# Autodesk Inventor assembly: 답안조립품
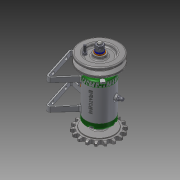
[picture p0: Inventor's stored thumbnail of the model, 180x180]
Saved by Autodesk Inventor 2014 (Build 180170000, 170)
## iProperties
Created: 2016-03
Part Number: 답안조립품
Document SubType Name: Assembly
Designer: SEC
Author: SEC
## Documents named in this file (16)
- C:\Documents and Settings\SEC\바탕 화면\460307V1022\답안조립품.iam
- C:\Documents and Settings\SEC\바탕 화면\460307V1022\본체.ipt
- C:\Documents and Settings\SEC\바탕 화면\460307V1022\V벨트풀리.ipt
- C:\Documents and Settings\SEC\바탕 화면\460307V1022\너트 M 8.ipt
- C:\Documents and Settings\SEC\바탕 화면\460307V1022\니플 M 6 x 0.75.ipt
- C:\Documents and Settings\SEC\바탕 화면\460307V1022\베어링 15 x 32 x 9.ipt
- C:\Documents and Settings\SEC\바탕 화면\460307V1022\볼트 M4 x 12.ipt
- C:\Documents and Settings\SEC\바탕 화면\460307V1022\볼트 M 6 x 8.ipt
- C:\Documents and Settings\SEC\바탕 화면\460307V1022\스프로킷.ipt
- C:\Documents and Settings\SEC\바탕 화면\460307V1022\스프링와셔 8.ipt
- C:\Documents and Settings\SEC\바탕 화면\460307V1022\오일 실 15 25 7.ipt
- C:\Documents and Settings\SEC\바탕 화면\460307V1022\와셔 6x11.5.ipt
- C:\Documents and Settings\SEC\바탕 화면\460307V1022\와셔 8x17.ipt
- C:\Documents and Settings\SEC\바탕 화면\460307V1022\축.ipt
- C:\Documents and Settings\SEC\바탕 화면\460307V1022\커버.ipt
- C:\Documents and Settings\SEC\바탕 화면\460307V1022\키 3 x 3 x 12.ipt
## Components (8 placed, 3 different names)
1. V벨트풀리:1
2. KS B 2023 6002 - 15 x 32 x 9:1
3. ISO 4762 M4 x 12:1
4. KS B 2023 6002 - 15 x 32 x 9:2
5. ISO 4762 M4 x 12:3
6. ISO 4762 M4 x 12:4
7. ISO 4762 M4 x 12:5
8. ISO 4762 M4 x 12:6
